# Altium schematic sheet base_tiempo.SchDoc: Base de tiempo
size A4; Revision: 1
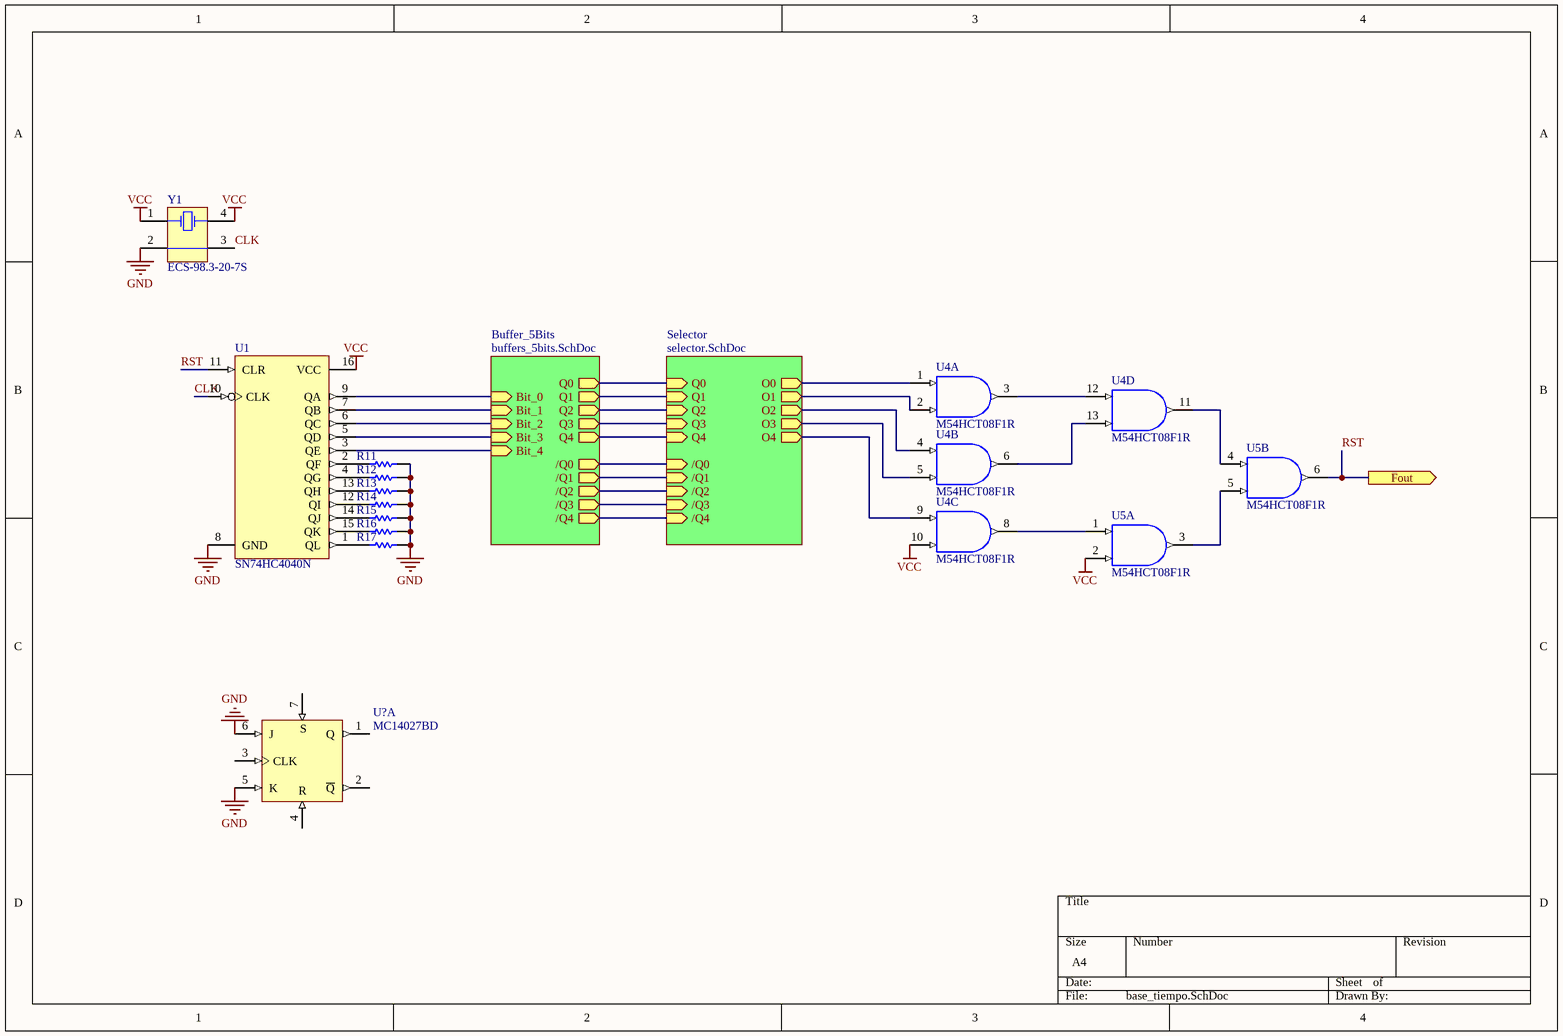
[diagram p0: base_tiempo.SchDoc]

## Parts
R11  Res Semi  [2012[0805]]  (value not drawn)
R12  Res Semi  [2012[0805]]  (value not drawn)
R13  Res Semi  [2012[0805]]  (value not drawn)
R14  Res Semi  [2012[0805]]  (value not drawn)
R15  Res Semi  [2012[0805]]  (value not drawn)
R16  Res Semi  [2012[0805]]  (value not drawn)
R17  Res Semi  [2012[0805]]  (value not drawn)
U1  SN74HC4040N  [N016]
U4  M54HCT08F1R  [CDIP14]  (parts A,B,C,D of 4)
U5  M54HCT08F1R  [CDIP14]  (parts A,B of 4)
U?  MC14027BD  [751B-05_N]  (part A of 2)
Y1  ECS-98.3-20-7S  [ECX-3S]

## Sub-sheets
Buffer_5Bits = buffers_5bits.SchDoc: Bit_0 (in), Bit_1 (in), Bit_2 (in), Bit_3 (in), Bit_4 (in), Q0 (out), Q1 (out), Q2 (out), Q3 (out), Q4 (out), /Q0 (out), /Q1 (out), /Q2 (out), /Q3 (out), /Q4 (out)
Selector = selector.SchDoc: Q0 (in), Q1 (in), Q2 (in), Q3 (in), Q4 (in), /Q0 (in), /Q1 (in), /Q2 (in), /Q3 (in), /Q4 (in), O0 (out), O1 (out), O2 (out), O3 (out), O4 (out)

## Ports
Fout (out)

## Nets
GND: R11.2 R12.2 R13.2 R14.2 R15.2 R16.2 R17.2 U1.8(GND) U4.7(GND) U5.7(GND) U?.5(K) U?.6(J) U?.8(GND) Y1.2(COM)
VCC: U1.16(VCC) U4.10(B) U4.14(VCC) U5.2(B) U5.14(VCC) Y1.1(OSC1) Y1.4(OSC2)
VDD: U?.16(VDD)
CLK: U1.10(CLK) Y1.3(COM)
RST: U1.11(CLR) U5.6(Y) ; port Fout
NetR11_1: R11.1 U1.2(QF)
NetR12_1: R12.1 U1.4(QG)
NetR13_1: R13.1 U1.13(QH)
NetR14_1: R14.1 U1.12(QI)
NetR15_1: R15.1 U1.14(QJ)
NetR16_1: R16.1 U1.15(QK)
NetR17_1: R17.1 U1.1(QL)
NetU1_3: U1.3(QE) ; sheet Buffer_5Bits/Bit_4
NetU1_5: U1.5(QD) ; sheet Buffer_5Bits/Bit_3
NetU1_6: U1.6(QC) ; sheet Buffer_5Bits/Bit_2
NetU1_7: U1.7(QB) ; sheet Buffer_5Bits/Bit_1
NetU1_9: U1.9(QA) ; sheet Buffer_5Bits/Bit_0
NetU4_1: U4.1(A) ; sheet Selector/O0
NetU4_2: U4.2(B) ; sheet Selector/O1
NetU4_3: U4.3(Y) U4.12(A)
NetU4_4: U4.4(A) ; sheet Selector/O2
NetU4_5: U4.5(B) ; sheet Selector/O3
NetU4_6: U4.6(Y) U4.13(B)
NetU4_8: U4.8(Y) U5.1(A)
NetU4_9: U4.9(A) ; sheet Selector/O4
NetU4_11: U4.11(Y) U5.4(A)
NetU5_3: U5.3(Y) U5.5(B)
(unnamed): sheet Buffer_5Bits/Q0, sheet Selector/Q0
(unnamed): sheet Buffer_5Bits/Q1, sheet Selector/Q1  [a separate net that carries the same name]
(unnamed): sheet Buffer_5Bits/Q2, sheet Selector/Q2  [a separate net that carries the same name]
(unnamed): sheet Buffer_5Bits/Q3, sheet Selector/Q3  [a separate net that carries the same name]
(unnamed): sheet Buffer_5Bits/Q4, sheet Selector/Q4  [a separate net that carries the same name]
(unnamed): sheet Buffer_5Bits//Q0, sheet Selector//Q0  [a separate net that carries the same name]
(unnamed): sheet Buffer_5Bits//Q1, sheet Selector//Q1  [a separate net that carries the same name]
(unnamed): sheet Buffer_5Bits//Q2, sheet Selector//Q2  [a separate net that carries the same name]
(unnamed): sheet Buffer_5Bits//Q3, sheet Selector//Q3  [a separate net that carries the same name]
(unnamed): sheet Buffer_5Bits//Q4, sheet Selector//Q4  [a separate net that carries the same name]

Not connected (* = marked no-connect by the designer): U? 1(Q) 2(~{Q}) 3(CLK) 4(R) 7(S)

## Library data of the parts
R11-R17 = Res Semi: Semiconductor Resistor; Value: 1K
U1 = SN74HC4040N: 12-Bit Asynchronous Binary Counter
U4 U5 = M54HCT08F1R: Quad 2-Input AND Gate
U? = MC14027BD: Dual J-K Flip-Flop
Y1 = ECS-98.3-20-7S: Crystal Oscillator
